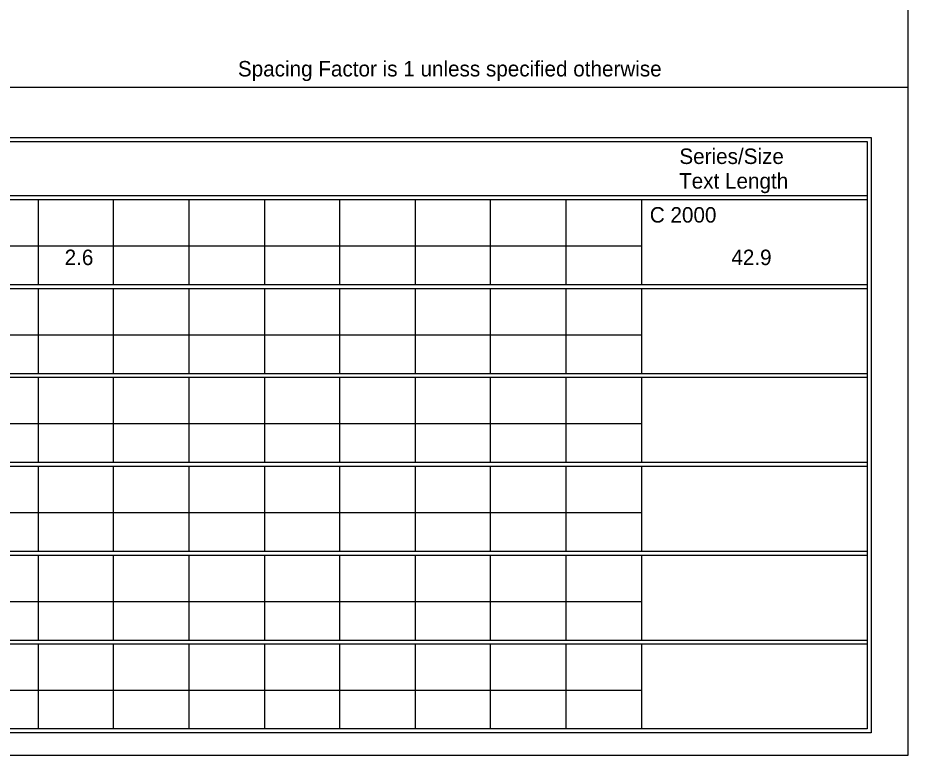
# Model space of a CAD drawing. Extents: x 57.2 to 85.4, y 153.3 to 173.4.
# Drawn here: x 64.05 to 69.72, y 153.34 to 158.04 of the extents above; entities that cross this region are included whole.
import ezdxf

# ---------------------------------------------------------------- set-up
doc = ezdxf.new("R2010")
doc.units = 0
doc.layers.add('Default', color=7, linetype='Continuous')

msp = doc.modelspace()

# ---------------------------------------------------------------- linework, layer by layer
at = {"layer": 'Default'}
for p, q in [((69.7172, 153.3441), (69.7172, 162.7348)), ((57.2061, 157.5985), (69.7172, 157.5985)), ((57.4226, 157.2766), (69.481, 157.2766)), ((57.4473, 157.252), (69.4564, 157.252)), ((69.4564, 157.252), (69.4564, 153.5114)), ((69.481, 157.2766), (69.481, 153.4868)), ((57.4473, 156.9074), (69.4564, 156.9074)), ((57.4473, 156.8828), (69.4564, 156.8828)), ((64.1753, 156.8828), (64.1753, 156.3414)), ((64.6527, 156.8828), (64.6527, 156.3414)), ((65.1351, 156.8828), (65.1351, 156.3414)), ((65.6174, 156.8828), (65.6174, 156.3414)), ((66.0948, 156.8828), (66.0948, 156.3414)), ((66.5771, 156.8828), (66.5771, 156.3414)), ((67.0545, 156.8828), (67.0545, 156.3414)), ((67.5369, 156.8828), (67.5369, 156.3414)), ((68.0192, 156.8828), (68.0192, 156.3414)), ((57.4473, 156.5875), (68.0192, 156.5875)), ((57.4473, 156.3414), (69.4564, 156.3414)), ((57.4473, 156.3168), (69.4564, 156.3168)), ((64.1753, 156.3168), (64.1753, 155.7754)), ((64.6527, 156.3168), (64.6527, 155.7754)), ((65.1351, 156.3168), (65.1351, 155.7754)), ((65.6174, 156.3168), (65.6174, 155.7754)), ((66.0948, 156.3168), (66.0948, 155.7754)), ((66.5771, 156.3168), (66.5771, 155.7754)), ((67.0545, 156.3168), (67.0545, 155.7754)), ((67.5369, 156.3168), (67.5369, 155.7754)), ((68.0192, 156.3168), (68.0192, 155.7754)), ((57.4473, 156.0215), (68.0192, 156.0215)), ((57.4473, 155.7754), (69.4564, 155.7754)), ((57.4473, 155.7508), (69.4564, 155.7508)), ((64.1753, 155.7508), (64.1753, 155.2094)), ((64.6527, 155.7508), (64.6527, 155.2094)), ((65.1351, 155.7508), (65.1351, 155.2094)), ((65.6174, 155.7508), (65.6174, 155.2094)), ((66.0948, 155.7508), (66.0948, 155.2094)), ((66.5771, 155.7508), (66.5771, 155.2094)), ((67.0545, 155.7508), (67.0545, 155.2094)), ((67.5369, 155.7508), (67.5369, 155.2094)), ((68.0192, 155.7508), (68.0192, 155.2094)), ((57.4473, 155.4555), (68.0192, 155.4555)), ((57.4473, 155.2094), (69.4564, 155.2094)), ((57.4473, 155.1848), (69.4564, 155.1848)), ((64.1753, 155.1848), (64.1753, 154.6434)), ((64.6527, 155.1848), (64.6527, 154.6434)), ((65.1351, 155.1848), (65.1351, 154.6434)), ((65.6174, 155.1848), (65.6174, 154.6434)), ((66.0948, 155.1848), (66.0948, 154.6434)), ((66.5771, 155.1848), (66.5771, 154.6434)), ((67.0545, 155.1848), (67.0545, 154.6434)), ((67.5369, 155.1848), (67.5369, 154.6434)), ((68.0192, 155.1848), (68.0192, 154.6434)), ((57.4473, 154.8895), (68.0192, 154.8895)), ((57.4473, 154.6434), (69.4564, 154.6434)), ((57.4473, 154.6188), (69.4564, 154.6188)), ((64.1753, 154.6188), (64.1753, 154.0774)), ((64.1753, 154.6188), (64.1753, 154.0774)), ((64.6527, 154.6188), (64.6527, 154.0774)), ((64.6527, 154.6188), (64.6527, 154.0774)), ((65.1351, 154.6188), (65.1351, 154.0774)), ((65.1351, 154.6188), (65.1351, 154.0774)), ((65.6174, 154.6188), (65.6174, 154.0774)), ((65.6174, 154.6188), (65.6174, 154.0774)), ((66.0948, 154.6188), (66.0948, 154.0774)), ((66.0948, 154.6188), (66.0948, 154.0774)), ((66.5771, 154.6188), (66.5771, 154.0774)), ((66.5771, 154.6188), (66.5771, 154.0774)), ((67.0545, 154.6188), (67.0545, 154.0774)), ((67.0545, 154.6188), (67.0545, 154.0774)), ((67.5369, 154.6188), (67.5369, 154.0774)), ((67.5369, 154.6188), (67.5369, 154.0774)), ((68.0192, 154.6188), (68.0192, 154.0774)), ((68.0192, 154.6188), (68.0192, 154.0774)), ((57.4473, 154.3235), (68.0192, 154.3235)), ((57.4473, 154.0774), (69.4564, 154.0774)), ((57.4473, 154.0528), (69.4564, 154.0528)), ((64.1753, 154.0528), (64.1753, 153.5114)), ((64.6527, 154.0528), (64.6527, 153.5114)), ((65.1351, 154.0528), (65.1351, 153.5114)), ((65.6174, 154.0528), (65.6174, 153.5114)), ((66.0948, 154.0528), (66.0948, 153.5114)), ((66.5771, 154.0528), (66.5771, 153.5114)), ((67.0545, 154.0528), (67.0545, 153.5114)), ((67.5369, 154.0528), (67.5369, 153.5114)), ((68.0192, 154.0528), (68.0192, 153.5114)), ((57.4473, 153.7575), (68.0192, 153.7575)), ((57.4473, 153.7575), (68.0192, 153.7575)), ((69.481, 153.4868), (57.4226, 153.4868)), ((69.4564, 153.5114), (57.4473, 153.5114)), ((57.2061, 153.3441), (69.7172, 153.3441))]:
    msp.add_line(p, q, dxfattribs=at)

# ---------------------------------------------------------------- texts
for s, height, p in [('Spacing Factor is 1 unless specified otherwise', 0.098425, (65.4474, 157.666)), ('Series/Size', 0.098435, (68.2596, 157.1086)), ('Text Length', 0.098435, (68.2578, 156.9518)), ('C 2000', 0.09843, (68.0712, 156.7355)), ('2.6', 0.09843, (64.3437, 156.4648)), ('42.9', 0.09843, (68.5908, 156.4648))]:
    msp.add_text(s, height=height, dxfattribs=at).set_placement(p)

doc.saveas('drawing.dxf')
